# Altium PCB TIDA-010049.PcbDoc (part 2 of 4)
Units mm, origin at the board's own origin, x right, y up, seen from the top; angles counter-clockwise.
Board outline 75 x 60 mm, 4 copper layers (Top Layer, GND, Supply, Bottom Layer), stack 1.565 mm thick; 309 components, 186 nets, 995 pads, 362 vias.
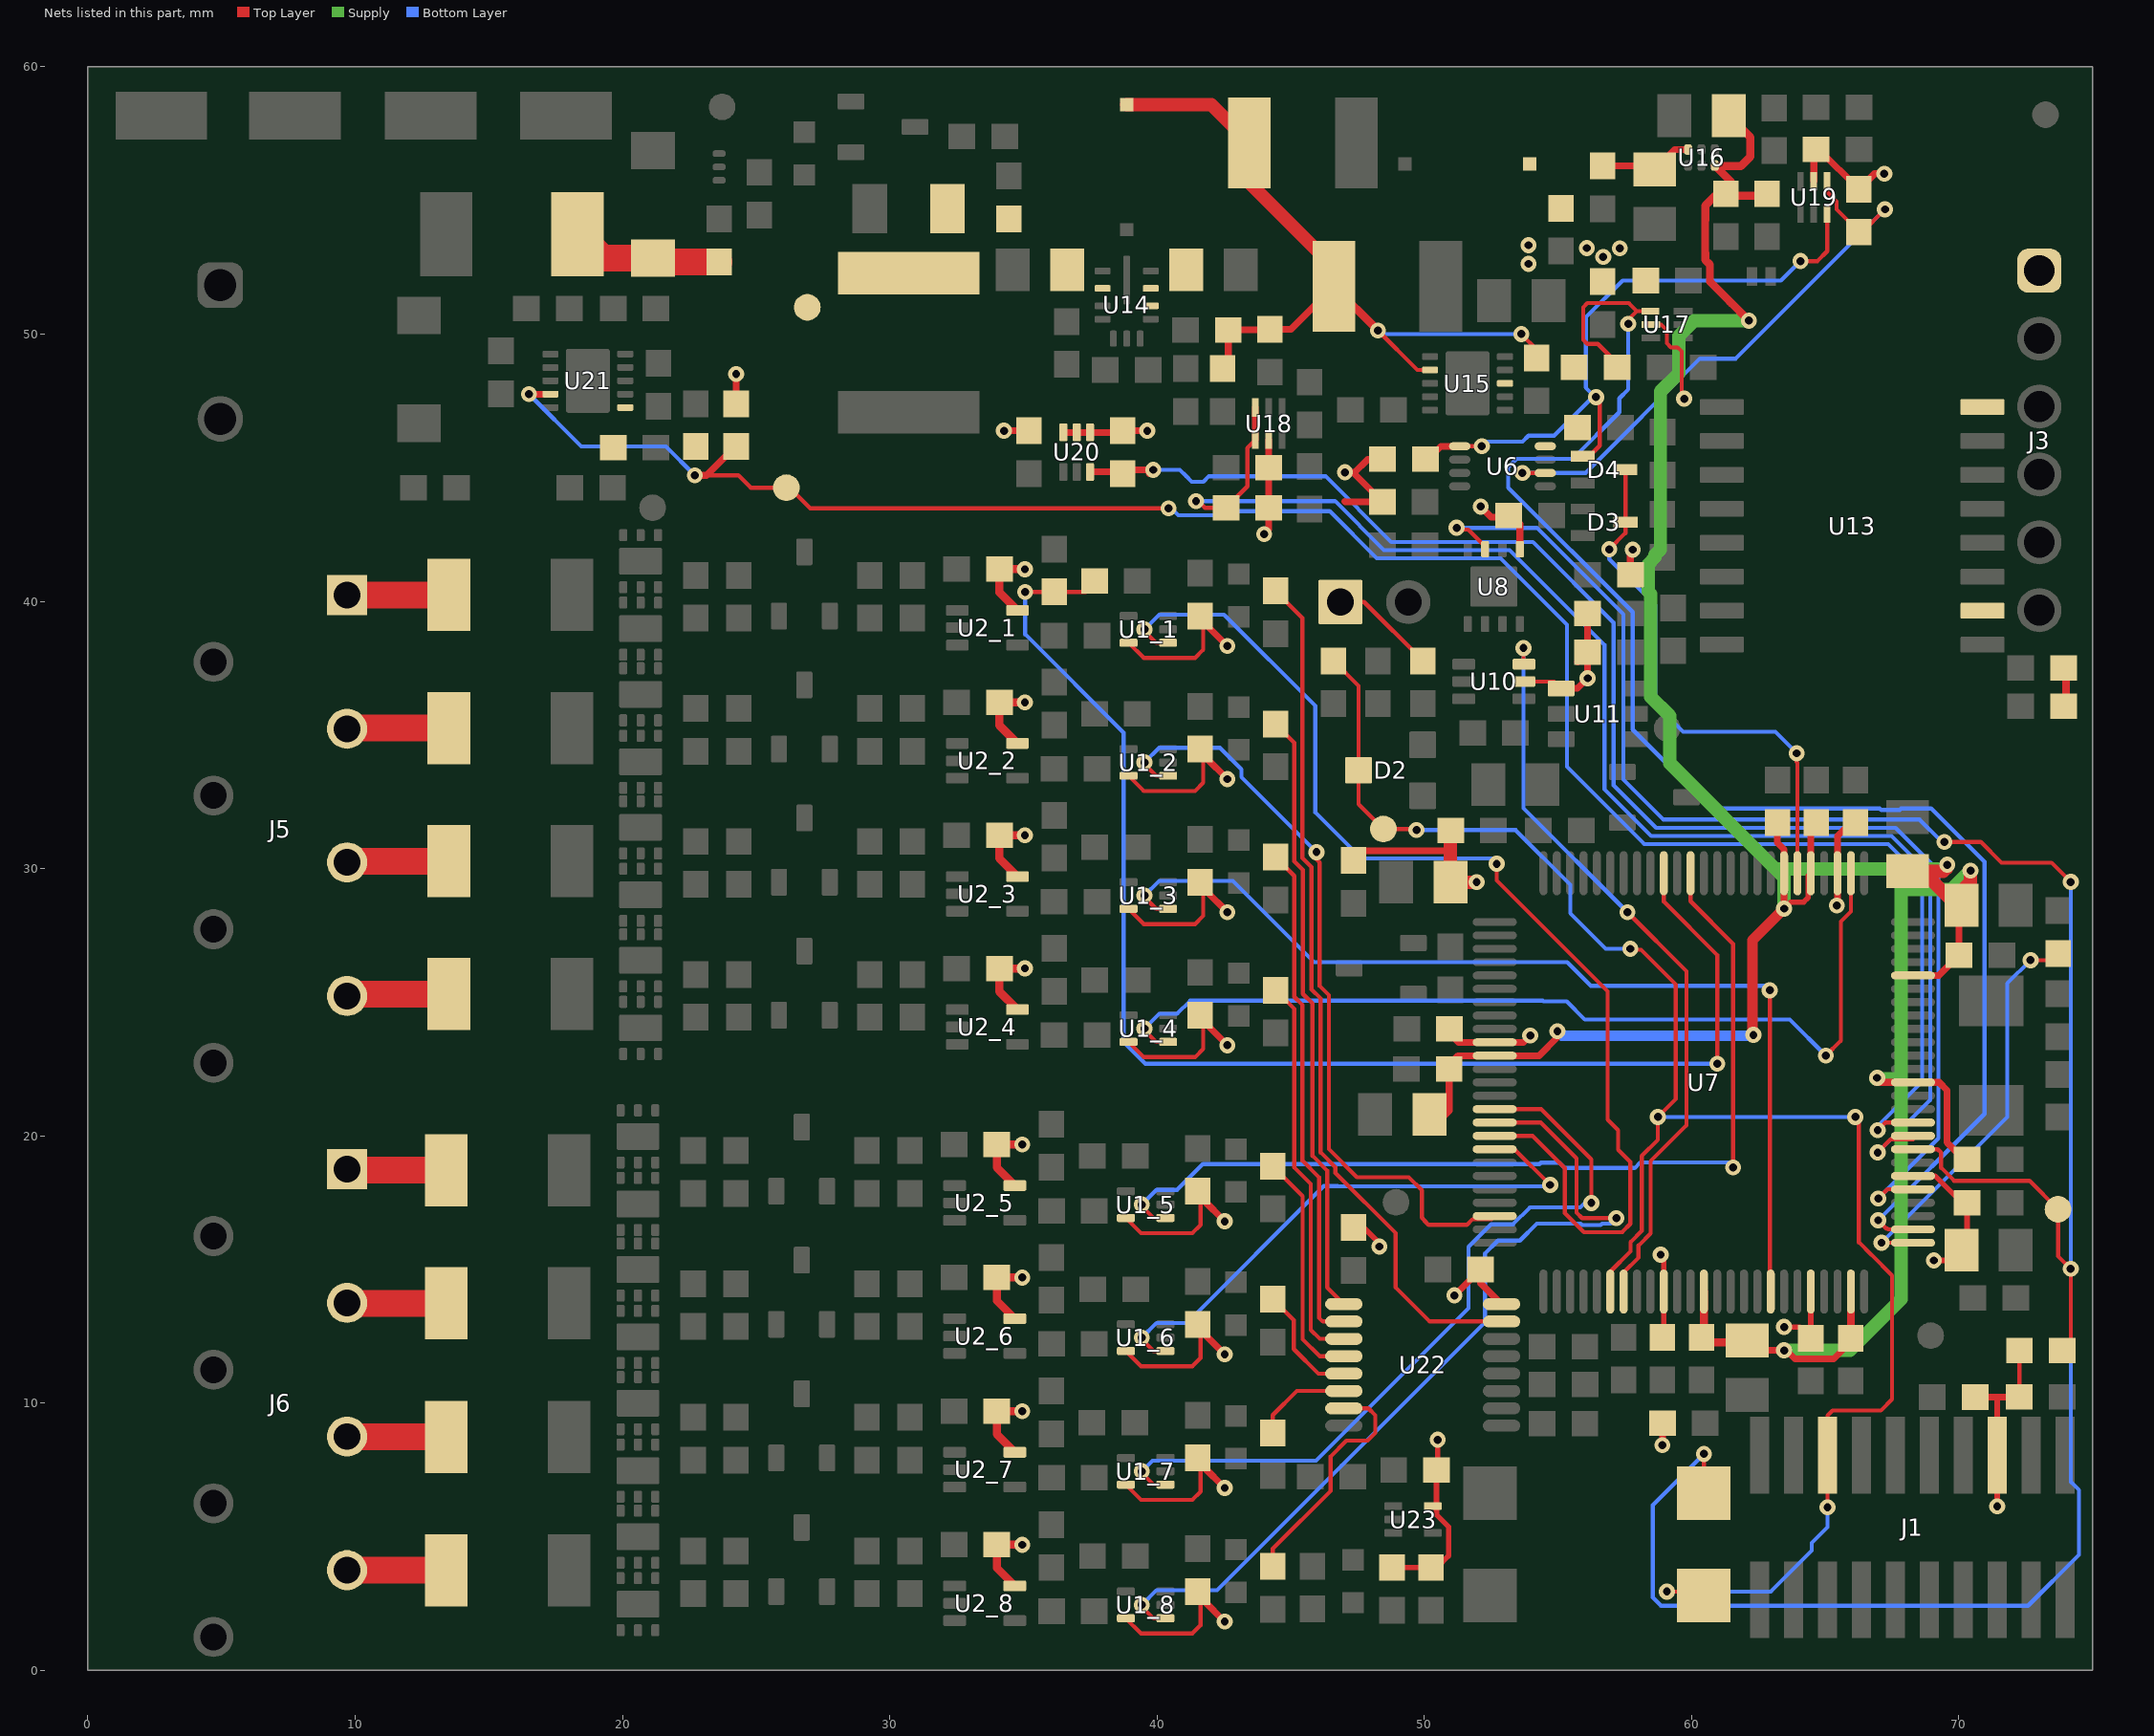
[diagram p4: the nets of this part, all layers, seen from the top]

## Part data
C1_1 C1_2 C1_3 C1_4 C1_5 C1_6 C1_7 C1_8: library part CMP-0007374-4, "CAP, CERM, 0.56 uF, 10 V, +/- 10%, X7R, 0603", Cap_Case=0603, Manufacturer=MuRata, Supplier Part Number 1=GRM188R71A564KA61D-ND, TempCo=X7R, Tolerance_%=10%, Value1=Unknown, Value2=10V, ValueDisplayed=0.56uF
C2_1 C2_2 C2_3 C2_4 C2_5 C2_6 C2_7 C2_8: library part CMP-0006812-4, "CAP, CERM, 100 pF, 10 V, +/- 10%, X7R, 0603", Cap_Case=0603, Manufacturer=AVX, Supplier Part Number 1=0603ZC101KAT2A-ND, TempCo=X7R, Tolerance_%=10%, Value1=Unknown, Value2=10V, ValueDisplayed=100pF
C3_1 C3_2 C3_3 C3_4 C3_5 C3_6 C3_7 C3_8 C4_1 C4_2 C4_3 C4_4 C4_5 C4_6 C4_7 C4_8 C5 C10 C11 C12 C13 C14 C15 C16 C21 C22 C23 C24 C25 C26 C28 C29 C30 C33 C34 C45 C46 C47 C48 C52 C53: library part CMP-0007378-5, "CAP, CERM, 0.1 uF, 16 V, +/- 10%, X7R, 0603", Cap_Case=0603, Manufacturer=MuRata, Supplier Part Number 1=490-1532-1-ND, TempCo=X7R, Tolerance_%=10%, Value1=Unknown, Value2=16V, ValueDisplayed=0.1uF
C6 C7 C8 C9 C19 C20: library part CMP-0064945-2, "CAP, CERM, 10 uF, 6.3 V,+/- 10%, X7R, 0805", Cap_Case=0805, Manufacturer="Taiyo Yuden", Supplier Part Number 1=587-2396-1-ND, TempCo=X7R, Tolerance_%=10%, Value1=Unknown, Value2=6.3V, ValueDisplayed=10uF
C17: library part CMP-0008377-2, "CAP, CERM, 22 uF, 10 V, +/- 20%, X7R, 0805", Cap_Case=0805, Manufacturer=MuRata, Supplier Part Number 1=81-GRM21BZ71A226ME5L, TempCo=X7R, Tolerance_%=20%, Value1=Unknown, Value2=10V, ValueDisplayed=22uF
C18 C27 C42: library part CMP-0007365-4, "CAP, CERM, 1 uF, 10 V, +/- 10%, X7R, 0603", Cap_Case=0603, Manufacturer=MuRata, Supplier Part Number 1=490-3899-1-ND, TempCo=X7R, Tolerance_%=10%, Value1="0.011 ohm", Value2=10V, ValueDisplayed=1uF
C31 C32: library part CMP-0007208-4, "CAP, CERM, 33 pF, 50 V, +/- 5%, C0G/NP0, 0603", Cap_Case=0603, Manufacturer=MuRata, Supplier Part Number 1=490-1415-1-ND, TempCo=C0G/NP0, Tolerance_%=5%, Value1=Unknown, Value2=50V, ValueDisplayed=33pF
C35: library part CMP-0009384-2, "CAP, CERM, 4.7 uF, 100 V, +/- 10%, X7R,", Cap_Case=2220_250, Manufacturer=TDK, Supplier Part Number 1=445-4526-1-ND, TempCo=X7R, Tolerance_%=10%, Value1="0.002349 ohm", Value2=100V, ValueDisplayed=4.7uF
C36 C37: library part CMP-0008249-2, "CAP, CERM, 0.22 uF, 100 V, +/- 10%, X7R, 0805", Cap_Case=0805, Manufacturer=MuRata, Supplier Part Number 1=GRM21AR72A224KAC5-ND, TempCo=X7R, Tolerance_%=10%, Value1=Unknown, Value2=100V, ValueDisplayed=0.22uF
C38: library part CMP-0007196-4, "CAP, CERM, 22 pF, 50 V, +/- 5%, C0G/NP0, 0603", Cap_Case=0603, Manufacturer=MuRata, Supplier Part Number 1=490-1411-1-ND, TempCo=C0G/NP0, Tolerance_%=5%, Value1=Unknown, Value2=50V, ValueDisplayed=22pF
C39 C40: library part CMP-0009348-2, "CAP, CERM, 22 uF, 25 V, +/- 20%, X7R,", Cap_Case=1812_280, Manufacturer=TDK, Supplier Part Number 1=445-1607-1-ND, TempCo=X7R, Tolerance_%=20%, Value1="0.002434 ohm", Value2=25V, ValueDisplayed=22uF
C41: library part CMP-0007112-4, "CAP, CERM, 4.7 uF, 6.3 V, +/- 10%, X7R, 0603", Cap_Case=0603, Manufacturer=Samsung, Supplier Part Number 1=1276-2087-1-ND, TempCo=X7R, Tolerance_%=10%, Value1=Unknown, Value2=6.3V, ValueDisplayed=4.7uF
C43 C44: library part CMP-0008315-2, "CAP, CERM, 10 uF, 10 V, +/- 10%, X7R, 0805", Cap_Case=0805, Manufacturer=MuRata, Supplier Part Number 1=490-3905-1-ND, TempCo=X7R, Tolerance_%=10%, Value1="0.003 ohm", Value2=10V, ValueDisplayed=10uF
C49 C50: library part CMP-0007469-4, "CAP, CERM, 0.1 uF, 100 V, +/- 10%, X7R, 0603", Cap_Case=0603, Manufacturer=MuRata, PartNumber=GRM188R72A104KA35D, Supplier Part Number 1=490-3285-1-ND, TempCo=X7R, Tolerance_%=10%, Value1=Unknown, Value2=100V, ValueDisplayed=0.1uF
C51: library part CMP-0007109-4, "CAP, CERM, 0.01 uF, 50 V, +/- 10%, X7R, 0603", Cap_Case=0603, Manufacturer="Samsung Electro-Mechanics", PartNumber=CL10B103KB8NCNC, Supplier Part Number 1=1276-1921-1-ND, TempCo=X7R, Tolerance_%=10%, Value1=Unknown, Value2=50V, ValueDisplayed=0.01uF
D1_1 D1_2 D1_3 D1_4 D1_5 D1_6 D1_7 D1_8: library part CMP-0002905-2, "LED, Green, SMD", Color=Green, Manufacturer="Wurth Elektronik", Value1=W, Value2=3.2V
D2: library part CMP-0086222-1, "Diode, Switching, 30 V, 0.13 A, SOT23, 3-Leads, Body 2.98x1.6mm, Pitch 0.95mm", Manufacturer=Panasonic, Value1=0.13A, Value2=0.55V
D3: library part CMP-0028454-2, "Diode, Schottky, 30 V, 0.2 A, SOT-523", Manufacturer="Diodes Inc.", Value1=0.2A, Value2=0.7V
D4: library part CMP-0077018-2, "Diode, Schottky, 30 V, 0.2 A, SOT-523", Manufacturer="Diodes Inc.", Value1=0.2A, Value2=1V
D5 D7: library part CMP-0085015-1, "Diode, TVS, Bi, 30 V, 48.4 Vc, 400 W, 8.3 A, SMA (non-polarized)", Manufacturer=Littelfuse, Value1=48.4V
D6: library part CMP-0076931-2, "Diode, Schottky, 30 V, 0.2 A, 1.00x0.50x0.60mm", Manufacturer="Diodes Inc.", Value1=0.2A, Value2=1V
D8: library part CMP-0002894-2, "LED, Green, SMD", Color=green, Manufacturer="Wurth Elektronik", PartNumber=150060VS75000, Value1=W, Value2=2V
D9: library part CMP-0002947-1, "LED, Red, SMD", Color=Red, Manufacturer="Wurth Elektronik", Power_TotalModule=72mW, Supplier Part Number 1=732-4978-1-ND, Value1=0.072W, Value2=2V
F1: library part CMP-0003488-1, "Fuse, 1.5 A, 125VAC/VDC, SMD", Irating_A=1.5A, Manufacturer=Littelfuse
FID1 FID2 FID3: library part CMP-0077181-1, "Fiducial mark.  There is nothing to buy or mount.", Manufacturer=N/A
H1 H2 H3 H4: library part CMP-0003620-1, "Bumpon, Hemisphere, 0.44 X 0.20, Clear", Manufacturer=3M, Supplier Part Number 1=SJ5303-7-ND
J1: library part CMP-0075640-2, "Header, 1.27mm, 10x2, Tin, SMT", Color=Black, Current_A=3.1A, Manufacturer=Samtec, Supplier Part Number 1=SAM8792-ND
J2: library part CMP-0075483-1, "Header, 100mil, 2x1, Gold, TH", Manufacturer=Samtec, Supplier Part Number 1=SAM8736-ND
J3: library part CMP-0054801-2, "Header, 2.54 mm, 6x1, Gold, TH", Color=Black, Manufacturer="Wurth Elektronik", Supplier Part Number 1=732-5319-ND
J4: library part CMP-0055529-1, "Terminal Block, 5mm, 2x1, R/A, TH", Color=Green, Current_A=16A, Manufacturer="Phoenix Contact", Supplier Part Number 1=277-2518-ND, Voltage_V=400V
J5 J6: library part CMP-0055509-1, "Terminal Block, 8x1, 2.5mm, Green, TH", Color=Green, Current_A=2A, Manufacturer="Phoenix Contact", Supplier Part Number 1=277-1800-ND, Voltage_V=300V
L1 L2: library part CMP-0064407-2, "Inductor, Shielded Drum Core, Ferrite, 18 uH, 0.7 A, 0.138 ohm, SMD", Manufacturer="Wurth Elektronik", Supplier Part Number 1=732-1106-1-ND, Value1="0.138 ohm", Value2=0.7A, ValueDisplayed=18uH
L3: library part CMP-0058743-1, "Inductor, Multilayer, Ferrite, 2.2 uH, 0.6 A, 0.34 ohm, SMD", Manufacturer=MuRata, Supplier Part Number 1=490-4994-1-ND, Value1="0.34 ohm", Value2=0.6A, ValueDisplayed=2.2uH
LBL1: library part CMP-0003625-1, "Thermal Transfer Printable Labels, 0.650\" W x 0.200\" H - 10,000 per roll", Manufacturer=Brady, Supplier Part Number 1=97C5133
LOGO1: library part CMP-0074844-1
Logo3: library part CMP-0074847-1, "FCC_disclaimer"
Logo4: library part CMP-0074769-1
Q1: library part CMP-0000824-1, "MOSFET, N-CH, 60 V, 2.2 A, YJK0003A (PICOSTAR-3)", Alternate Manufacturer=None, Manufacturer="Texas Instruments", Supplier Part Number 1=296-44374-1-ND, Value1=0.07, Value2="11 nC"
R1_1 R1_2 R1_3 R1_4 R1_5 R1_6 R1_7 R1_8 R4_1 R4_2 R4_3 R4_4 R4_5 R4_6 R4_7 R4_8 R23: library part CMP-0025752-3, "RES, 200, 5%, 0.1 W, 0603", Manufacturer=Vishay-Dale, Power_W=100mW, Supplier Part Number 1=541-200GCT-ND, TempCo="200 ppm/C", Tolerance_%=5%, Value2=0.1W, Value_Code=200R, ValueDisplayed=200
R2_1 R2_2 R2_3 R2_4 R2_5 R2_6 R2_7 R2_8: library part CMP-0016428-1, "RES, 4.99 k, 1%, 0.75 W, AEC-Q200 Grade 0, 2010", Manufacturer=Vishay-Dale, Power_W=750mW, Supplier Part Number 1=541-4.99KACCT-ND, TempCo="100 ppm/C", Tolerance_%=1%, Value2=0.75W, Value_Code=4k99, ValueDisplayed=4.99k
R3_1 R3_2 R3_3 R3_4 R3_5 R3_6 R3_7 R3_8: library part CMP-0022867-5, "RES, 1.13 k, 1%, 0.1 W, 0603", Manufacturer=Yageo, Power_W=100mW, Supplier Part Number 1=311-1.13KHRCT-ND, TempCo="100 ppm/C", Tolerance_%=1%, Value2=0.1W, Value_Code=1k13, ValueDisplayed=1.13k
R5_1 R5_2 R5_3 R5_4 R5_5 R5_6 R5_7 R5_8: library part CMP-0023233-5, "RES, 66.5, 1%, 0.1 W, 0603", Manufacturer=Yageo, Power_W=100mW, Supplier Part Number 1=311-66.5HRCT-ND, TempCo="100 ppm/C", Tolerance_%=1%, Value2=0.1W, Value_Code=66R5, ValueDisplayed=66.5
R6_1 R6_2 R6_3 R6_4 R6_5 R6_6 R6_7 R6_8 R64: library part CMP-0023284-5, "RES, 806, 1%, 0.1 W, 0603", Manufacturer=Yageo, Power_W=100mW, Supplier Part Number 1=311-806HRCT-ND, TempCo="100 ppm/C", Tolerance_%=1%, Value2=0.1W, Value_Code=806R, ValueDisplayed=806
R7_1 R7_2 R7_3 R7_4 R7_5 R7_6 R7_7 R7_8: library part CMP-0022990-5, "RES, 2.49 k, 1%, 0.1 W, 0603", Manufacturer=Yageo, Power_W=100mW, Supplier Part Number 1=311-2.49KHRCT-ND, TempCo="100 ppm/C", Tolerance_%=1%, Value2=0.1W, Value_Code=2k49, ValueDisplayed=2.49k
R8 R16 R22 R24 R27 R57 R58 R59 R63: library part CMP-0025918-5, "RES, 3.3 k, 5%, 0.1 W, 0603", Manufacturer=Yageo, Power_W=100mW, Supplier Part Number 1=311-3.3KGRCT-ND, TempCo="100 ppm/C", Tolerance_%=5%, Value2=0.1W, Value_Code=3k30, ValueDisplayed=3.3k
R9 R10 R11 R12 R13 R15 R26: library part CMP-0025886-5, "RES, 10 k, 5%, 0.1 W, 0603", Manufacturer=Yageo, Power_W=100mW, Supplier Part Number 1=311-10KGRCT-ND, TempCo="100 ppm/C", Tolerance_%=5%, Value2=0.1W, Value_Code=10k0, ValueDisplayed=10k
R14 R17 R19 R21 R28 R29 R30 R37 R38 R39 R42 R49 R50 R51 R56: library part CMP-0025925-5, "RES, 47 k, 5%, 0.1 W, 0603", Manufacturer=Yageo, Power_W=100mW, Supplier Part Number 1=311-47KGRCT-ND, TempCo="100 ppm/C", Tolerance_%=5%, Value2=0.1W, Value_Code=47k0, ValueDisplayed=47k
R18: library part CMP-0025821-4, "RES, 4.7, 5%, 0.1 W, AEC-Q200 Grade 0, 0603", Manufacturer=Vishay-Dale, Power_W=100mW, Supplier Part Number 1=541-4.7GCT-ND, TempCo="200 ppm/C", Tolerance_%=5%, Value2=0.1W, Value_Code=4R70, ValueDisplayed=4.7
R20: library part CMP-0022984-5, "RES, 2.21 k, 1%, 0.1 W, 0603", Manufacturer=Yageo, Power_W=100mW, Supplier Part Number 1=311-2.21KHRCT-ND, TempCo="100 ppm/C", Tolerance_%=1%, Value2=0.1W, Value_Code=2k21, ValueDisplayed=2.21k
R25: library part CMP-0025899-5, "RES, 1.0 k, 5%, 0.1 W, 0603", Manufacturer=Yageo, Power_W=100mW, Supplier Part Number 1=311-1.0KGRCT-ND, TempCo="100 ppm/C", Tolerance_%=5%, Value2=0.1W, Value_Code=1k00, ValueDisplayed=1.0k
R31: library part CMP-0023291-5, "RES, 82.5 k, 1%, 0.1 W, 0603", Manufacturer=Yageo, Power_W=100mW, Supplier Part Number 1=311-82.5KHRCT-ND, TempCo="100 ppm/C", Tolerance_%=1%, Value2=0.1W, Value_Code=82k5, ValueDisplayed=82.5k
R32: library part CMP-0022900-4, "RES, 1.00, 1%, 0.1 W, 0603", Manufacturer=Yageo, Power_W=100mW, Supplier Part Number 1=311-1.00HRCT-ND, TempCo="200 ppm/C", Tolerance_%=1%, Value2=0.1W, Value_Code=1R00, ValueDisplayed=1.00
R33 R36 R46 R47 R48 R55 R62: library part CMP-0022944-5, "RES, 24.9 k, 1%, 0.1 W, 0603", Manufacturer=Yageo, Power_W=100mW, Supplier Part Number 1=311-24.9KHRCT-ND, TempCo="100 ppm/C", Tolerance_%=1%, Value2=0.1W, Value_Code=24k9, ValueDisplayed=24.9k
R34: library part CMP-0023026-5, "RES, 31.6 k, 1%, 0.1 W, 0603", Manufacturer=Yageo, Power_W=100mW, Supplier Part Number 1=311-31.6KHRCT-ND, TempCo="100 ppm/C", Tolerance_%=1%, Value2=0.1W, Value_Code=31k6, ValueDisplayed=31.6k
R35: library part CMP-0023238-5, "RES, 68.1 k, 1%, 0.1 W, 0603", Manufacturer=Yageo, Power_W=100mW, Supplier Part Number 1=311-68.1KHRCT-ND, TempCo="100 ppm/C", Tolerance_%=1%, Value2=0.1W, Value_Code=68k1, ValueDisplayed=68.1k
R40: library part CMP-0023176-5, "RES, 53.6 k, 1%, 0.1 W, 0603", Manufacturer=Yageo, Power_W=100mW, Supplier Part Number 1=311-53.6KHRCT-ND, TempCo="100 ppm/C", Tolerance_%=1%, Value2=0.1W, Value_Code=53k6, ValueDisplayed=53.6k
R41: library part CMP-0022941-4, "RES, 249 k, 1%, 0.1 W, 0603", Manufacturer=Yageo, Power_W=100mW, Supplier Part Number 1=311-249KHRCT-ND, TempCo="100 ppm/C", Tolerance_%=1%, Value2=0.1W, Value_Code=249k
R43: library part CMP-0022872-5, "RES, 1.24 k, 1%, 0.1 W, 0603", Manufacturer=Yageo, Power_W=100mW, Supplier Part Number 1=311-1.24KHRCT-ND, TempCo="100 ppm/C", Tolerance_%=1%, Value2=0.1W, Value_Code=1k24, ValueDisplayed=1.24k
R44: library part CMP-0022982-5, "RES, 2.15 k, 1%, 0.1 W, 0603", Manufacturer=Yageo, Power_W=100mW, Supplier Part Number 1=311-2.15KHRCT-ND, TempCo="100 ppm/C", Tolerance_%=1%, Value2=0.1W, Value_Code=2k15, ValueDisplayed=2.15k
R45: library part CMP-0022858-4, "RES, 196 k, 1%, 0.1 W, 0603", Manufacturer=Yageo, Power_W=100mW, Supplier Part Number 1=311-196KHRCT-ND, TempCo="100 ppm/C", Tolerance_%=1%, Value2=0.1W, Value_Code=196k
R52: library part CMP-0023184-4, "RES, 562 k, 1%, 0.1 W, 0603", Manufacturer=Yageo, Power_W=100mW, Supplier Part Number 1=311-562KHRCT-ND, TempCo="100 ppm/C", Tolerance_%=1%, Value2=0.1W, Value_Code=562k
R53: library part CMP-0022792-5, "RES, 13.0 k, 1%, 0.1 W, 0603", Manufacturer=Yageo, Power_W=100mW, Supplier Part Number 1=311-13.0KHRCT-ND, TempCo="100 ppm/C", Tolerance_%=1%, Value2=0.1W, Value_Code=13k0, ValueDisplayed=13.0k
R54: library part CMP-0023279-5, "RES, 7.50 k, 1%, 0.1 W, 0603", Manufacturer=Yageo, Power_W=100mW, Supplier Part Number 1=311-7.50KHRCT-ND, TempCo="100 ppm/C", Tolerance_%=1%, Value2=0.1W, Value_Code=7k50, ValueDisplayed=7.50k
R60: library part CMP-0022824-4, "RES, 165 k, 1%, 0.1 W, 0603", Manufacturer=Yageo, Power_W=100mW, Supplier Part Number 1=311-165KHRCT-ND, TempCo="100 ppm/C", Tolerance_%=1%, Value2=0.1W, Value_Code=165k
R61: library part CMP-0017903-2, "RES, 14.7 k, 1%, 0.25 W, 1206", Manufacturer="Yageo America", Power_W=250mW, Supplier Part Number 1=311-14.7KFRCT-ND, TempCo="100 ppm/C", Tolerance_%=1%, Value2=0.25W, Value_Code=14k7, ValueDisplayed=14.7k
S1 S2: library part CMP-0002210-1, "Switch, Tactile, SPST-NO, 0.05A, 12V, SMD", CurrentRating_mA=50A, Manufacturer="C&K Components", Supplier Part Number 1=CKN10388CT-ND
TP6 TP7 TP8 TP9 TP15 TP19 TP20: library part CMP-0003825-1, "1mm Test Point, SMT", Manufacturer=Any
TP11 TP12 TP13 TP14: library part CMP-0055152-1, "Test Point, Miniature, SMT", Manufacturer=Keystone, Supplier Part Number 1=36-5015TR-ND
U1_1 U1_2 U1_3 U1_4 U1_5 U1_6 U1_7 U1_8 U23: library part CMP-0051312-3, "Single Bus Buffer Gate With 3-State Outputs, DRL0005A, LARGE T&R", Alternate Manufacturer="Texas Instruments", F @ Nom Voltage(Max)(Mhz)=150, Generic Part Number=SN74LVC1G125, ICC @ Nom Voltage(Max)(mA)=0.01, Operating Temperature Range(C)="-40 to 125,-40 to 85", Rating=Catalog, tpd @ Nom Voltage(Max)(ns)=9,5.5,4.5,4, Voltage(Nom)(V)=1.8,2.5,3.3,5
U2_1 U2_2 U2_3 U2_4 U2_5 U2_6 U2_7 U2_8: library part CMP-0081556-1, "Low-Power, Rail-to-Rail In and Out, 1-MHz Operational Amplifier, DCK0005A (SOT-SC70-5)", Alternate Manufacturer="Texas Instruments", Alternate PartNumber=TLV9001IDCKT
U3_1 U3_2 U3_3 U3_4 U3_5 U3_6 U3_7 U3_8 U4_1 U4_2 U4_3 U4_4 U4_5 U4_6 U4_7 U4_8: library part CMP-0077837-1, "5-V Precision Surge Protection Clamp, DRV0006A (WSON-6)", Alternate Manufacturer="Texas Instruments"
U5_1 U5_2 U5_3 U5_4 U5_5 U5_6 U5_7 U5_8 U24: library part CMP-0084728-1, "Programmable Shunt Regulator with Optimized Reference Current, DBZ0003A (SOT-23-3)", Alternate Manufacturer="Texas Instruments"
U6: library part CMP-0051919-2, "Dual 2-Input NAND Gate with Schmitt-Trigger Inputs, DCU0008A (VSSOP-8)", F @ Nom Voltage(Max)(Mhz)=150, Generic Part Number=SN74LVC2G132, ICC @ Nom Voltage(Max)(mA)=0.01, Manufacturer="Texas Instruments", Operating Temperature Range="-40 to 125 C", Rating=Catalog, tpd @ Nom Voltage(Max)(ns)=16,7.5,6,5, Voltage(Nom)(V)=1.8,2.5,3.3,5
U7: library part CMP-0076634-2, "16- and 32-Bit RISC Flash Microcontroller, PZ0100A (LQFP-100)", Alternate Manufacturer="Texas Instruments"
U8: library part CMP-0013381-4, "High-Accuracy Voltage Supervisor With Programmable Window Watchdog Timer, DRB0008A (VSON-8)", Alternate Manufacturer="Texas Instruments", Alternate PartNumber=TPS3852H33DRBT, Operating Temperature Range="-40 to 125 C", Rating=Catalog
U9: library part CMP-0032500-1, "3.0 V, 50 ppm / degC, 50 uA Series (Bandgap) Voltage Reference, -40 to 125 degC, 3-pin SOT-23 (DBZ), Green (RoHS & no Sb/Br)", Manufacturer="Texas Instruments", Rating=Catalog, Temp Coeff(Max)(ppm/ degree C)=50, Temp Coeff(Typ)(ppm/ degree C)=20
U10: library part CMP-0051216-3, "Single 3-Input Positive-AND Gate, DCK0006A (SOT-SC70-6)", F @ Nom Voltage(Max)(Mhz)=150, Generic Part Number=SN74LVC1G11, ICC @ Nom Voltage(Max)(mA)=0.01, Manufacturer="Texas Instruments", Operating Temperature Range="-40 to 125,-40 to 85 C", Rating=Catalog, tpd @ Nom Voltage(Max)(ns)=20,7.8,6.2,4.6, Voltage(Nom)(V)=1.8,2.5,3.3,5
U11: library part CMP-0077265-1, "5.5-V, 2-A, 80 mohm Low Leakage Load Switch with RCB and Programmable Rise Time, DBV0006A (SOT-23-6)", Alternate Manufacturer="Texas Instruments", Alternate PartNumber=TPS22917DBVT
U12: library part CMP-0084725-1, "Programmable Shunt Regulator with Optimized Reference Current, DBZ0003A (SOT-23-3)", Alternate Manufacturer="Texas Instruments"
U13: library part CMP-0076065-3, "Automotive, High Speed, Robust EMC Quad-Channel Digital Isolators, DW0016B (SOIC-16)", Alternate Manufacturer="Texas Instruments", Alternate PartNumber=ISO7741FQDWQ1, Operating Temperature Range="-40 to 125 C", Rating=Automotive
U14: library part CMP-0080116-3, "65-V 0.6-A Synchronous Step-Down Converter, RNX0012B (VQFN-HR-12)", Alternate Manufacturer="Texas Instruments", Alternate PartNumber=LMR36006BRNXR
U15: library part CMP-0013400-5, "3V-65V Input, 500mA Synchronous Buck Converter With Ultra-Low Iq, DRC0010J (VSON-10)", Alternate Manufacturer="Texas Instruments", Alternate PartNumber=LM5166YDRCT, Operating Temperature Range="-40 to 150 C", Rating=Catalog
U16: library part CMP-0037816-3, "2 MHz Ultra Small Step Down Converter with DCS-Control in 1x1.5 SON Package, DRY0006A (USON-6)", Manufacturer="Texas Instruments", Operating Temperature Range="-40 to 125 C", Rating=Catalog, Switch Current Limit(Typ)(A)=0.84
U17 U18 U19: library part CMP-0074243-1, "High-Voltage (18V) Window Comparator with Over- and Undervoltage Detection, DSE0006A (WSON-6)", Alternate Manufacturer="Texas Instruments", Alternate PartNumber=TPS3700DSET
U20: library part CMP-0074324-2, "Pin-Selectable Trip Point 1.4V-Capable Family of Temperature Switches, DRL0006A (SOT-OTHER-6)", Alternate Manufacturer="Texas Instruments", Alternate PartNumber=TMP302CDRLT
U21: library part CMP-0013390-6, "60-V, 800-mA Industrial eFuse with Integrated Reverse Polarity Protection, DRC0010J (VSON-10)", Alternate Manufacturer="Texas Instruments", Alternate PartNumber=TPS26624DRCT, Operating Temperature Range="-40 to 125 C", Rating=Catalog
U22: library part CMP-0053860-1, "8-Bit Shift Registers With Output Registers, PW0016A, TUBE", F @ Nom Voltage(Max)(Mhz)=110, Generic Part Number=SN74AHC594, ICC @ Nom Voltage(Max)(mA)=0.04, Manufacturer="Texas Instruments", Operating Temperature Range(C)="-40 to 125", Rating=Catalog, tpd @ Nom Voltage(Max)(ns)="13.9, 10.1", Voltage(Nom)(V)="3.3, 5"
Y1: library part CMP-0004648-3, "Crystal, 16 MHz, 18 pF, SMD", Frequency_Fixed=16MHz, Frequency Stability=+/-30ppm, Manufacturer="Abracon Corporation", Supplier Part Number 1=535-10638-1-ND
ZZ1: library part CMP-0003616-3
ZZ2: library part CMP-0077236-1
ZZ3: library part CMP-0077237-1
ZZ4: library part CMP-0077238-1

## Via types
v1: diameter 0.6, hole 0.3, Top Layer to Bottom Layer, 318 vias
v2: diameter 0.5, hole 0.2, Top Layer to Bottom Layer, 44 vias

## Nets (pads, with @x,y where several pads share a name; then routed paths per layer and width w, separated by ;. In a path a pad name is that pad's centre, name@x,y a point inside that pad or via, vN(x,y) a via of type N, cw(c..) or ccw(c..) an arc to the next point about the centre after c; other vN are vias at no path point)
1.25V: C6.1 C7.1 C8.1 C9.1 C10.1 C11.1 C12.1 C13.1 C14.1 C15.1 C16.1 C41.1 L3.2 R40.1 U7.13 U7.21 U7.30 U7.32 U7.61 U7.88 U7.99 U16.6 | length 121.6
  Top Layer w0.152: 61.432,51.099 61.432,51.21
  Top Layer w0.2: v1(63.458,28.5) 63.706,28.748 64.192,28.748 64.36,28.916 64.36,29.727 U7.30@64.458,29.825
  Top Layer w0.254: C8.1@50.74,20.75 50.929,20.939 C14.1@50.929,22.506 ; C14.1@50.758,22.5 51.258,23 U7.61@52.633,23 54.294,23 54.98,23.686 v1(54.98,23.912) ; C9.1@62.083,12.341 62.158,12.266 62.449,11.975 v1(63.458,11.975) 63.545,11.975 63.867,11.653 65.311,11.653 C16.1@65.958,12.3 ; C13.1@62.958,31.718 63.208,31.468 63.208,30.968 63.458,30.718 U7.32@63.458,29.825 v1(63.458,28.5) ; U7.30@64.458,29.825 C12.1@64.458,31.718 ; v1(66.939,22.173) 66.939,22 U7.13@68.283,22 69.258,22 69.558,21.7 69.558,19.75 C10.1@70.308,19 ; U7.21@68.283,26 69.244,26 C11.1@70.008,26.764 C6.1@70.008,28.541
  Top Layer w0.3: U7.88@60.458,14.175 60.458,12.263 60.461,12.266 C9.1@62.158,12.266 ; U16.6@60.866,56.306 U16.6@60.893,56.278 ; L3.2@61.382,58.174 62.199,57.356 62.199,56.641 61.836,56.278 U16.6@60.893,56.278 ; v1(62.142,50.5) 61.432,51.21 60.683,51.959 60.683,52.599 60.507,52.775 60.507,53.02 60.506,53.022 60.506,54.271 60.507,54.272 60.507,54.799 60.888,55.18 C41.1@61.458,55.18 ; R40.1@62.823,55.246 62.757,55.18 C41.1@61.458,55.18 ; C16.1@65.958,12.3 C16.1@65.958,12.432 U7.99@65.958,14.175 ; U16.6@60.893,56.278 61.458,55.714 C41.1@61.458,55.18
  Top Layer w0.4: v1(62.313,23.776) 62.271,23.818 62.271,27.313 v1(63.458,28.5)
  Top Layer w0.5: C7.1@68.075,29.902 C7.1@68.647,29.902 ; v1(69.563,30.144) 69.563,30.048 69.417,29.902 C7.1@68.647,29.902 ; v1(70.433,29.925) 70.433,29.505 70.008,29.08 70.008,28.541 C7.1@68.647,29.902
  Supply w0.254: v1@66.894,22.128 v1(66.939,22.173)
  Supply w0.5: v1(62.142,50.5) 60.093,50.5 59.522,49.929 59.522,48.536 58.833,47.847 58.833,41.929 58.634,41.73 58.634,41.639 58.371,41.375 58.371,40.374 58.468,40.277 58.468,36.43 59.181,35.717 59.181,33.947 63.137,29.99 ; v1@63.458,11.975 65.927,11.975 67.839,13.887 67.839,22.125 ; v1@63.458,28.5 63.458,29.669 63.137,29.99 ; v1@66.894,22.128 67.837,22.128 67.839,22.125 ; v1(69.563,30.144) 69.41,29.99 63.137,29.99 ; v1(70.433,29.925) 69.717,29.208 67.839,29.208 67.839,22.125
  Bottom Layer w0.4: v1(54.98,23.912) 55.142,23.75 62.287,23.75 v1(62.313,23.776)
3.3V: C3_1.1 C3_2.1 C3_3.1 C3_4.1 C3_5.1 C3_6.1 C3_7.1 C3_8.1 C4_1.1 C4_2.1 C4_3.1 C4_4.1 C4_5.1 C4_6.1 C4_7.1 C4_8.1 C5.1 C19.1 C20.1 C21.1 C22.1 C23.1 C24.1 C25.1 C26.1 C30.1 C33.1 C44.1 C45.1 C46.1 C47.1 C48.1 C52.1 C53.1 J1.5 J2.1 L2.2 R9.2 R10.2 R11.2 R12.2 R13.2 R14.2 R15.2 R16.1 R18.1 R19.2 R23.2 R30.1 R32.2 R37.1 R38.2 R39.2 R42.1 R45.2 R49.2 R50.1 R56.1 U1_1.5 U1_2.5 U1_3.5 U1_4.5 U1_5.5 U1_6.5 U1_7.5 U1_8.5 U2_1.5 U2_2.5 U2_3.5 U2_4.5 U2_5.5 U2_6.5 U2_7.5 U2_8.5 U6.8 U7.6 U7.28 U7.60 U7.85 U7.96 U8.1 U10.5 U11.1 U15.8 U16.3 U17.2 U18.2 U19.2 U20.4 U20.5 U20.6 U22.16 U23.5 | length 149
  Top Layer w0.152: U1_8.5@38.835,1.95 39.404,1.38 41.321,1.38 41.631,1.69 C4_8.1@41.631,2.511 ; U1_6.5@38.835,11.95 39.404,11.38 41.321,11.38 41.631,11.69 C4_6.1@41.631,12.511 ; U1_5.5@38.835,16.928 39.404,16.359 41.321,16.359 41.631,16.668 C4_5.1@41.631,17.489 ; U1_7.5@38.835,6.95 39.404,6.38 41.321,6.38 41.631,6.69 C4_7.1@41.631,7.511 ; U1_4.5@38.935,23.514 39.505,22.944 41.421,22.944 41.731,23.254 C4_4.1@41.731,24.075 ; U1_3.5@38.935,28.493 39.505,27.923 41.421,27.923 41.731,28.233 C4_3.1@41.731,29.053 ; U1_2.5@38.935,33.471 39.505,32.902 41.421,32.902 41.731,33.211 C4_2.1@41.731,34.032 ; U1_1.5@38.935,38.45 39.505,37.88 41.421,37.88 41.731,38.19 C4_1.1@41.731,39.011 ; J2.1@46.861,39.974 47.746,39.974 R19.2@49.949,37.771 ; U10.5@53.725,37 54.858,37 U11.1@55.118,36.74 ; U17.2@58.483,50.355 58.857,50.355 59.073,50.139 59.073,49.656 59.229,49.5 59.478,49.5 59.627,49.352 v1@59.627,47.461 ; v1@59.721,47.366 v1(59.721,47.58) ; R11.2@72.249,10.225 R11.2@72.258,10.234 72.264,10.24 R14.2@72.264,11.975
  Top Layer w0.203: R56.1@47.347,16.568 47.726,16.568 48.316,15.979 v1(48.316,15.859) ; R10.2@48.791,3.85 R13.2@50.249,3.85 50.471,3.85 50.908,4.286 50.908,5.373 50.454,5.827 50.454,7.287 50.5,7.334 v1(50.5,8.63) ; v1(58.843,15.555) 58.958,15.555 U7.85@58.958,14.175 C24.1@58.958,12.263 ; v1(63.458,12.85) 64.04,12.85 C25.1@64.458,12.432 ; C25.1@64.458,12.3 C25.1@64.458,12.432 ; U7.96@64.458,14.175 C25.1@64.458,12.432 ; U7.6@68.283,18.5 69.108,18.5 70.108,17.5 C21.1@70.308,17.5 70.308,15.859 C20.1@70.442,15.725 ; v1(69.065,15.341) 69.708,15.341 C20.1@70.092,15.725 ; v1(71.433,6.136) J1.5@71.433,8.055 71.433,10.225 ; 71.433,10.234 R11.2@72.258,10.234
  Top Layer w0.254: R49.2@24.256,47.42 v1(24.256,48.501) ; v1(34.274,46.38) C48.1@35.208,46.38 ; U20.6@36.494,46.32 U20.5@36.994,46.32 U20.4@37.494,46.32 38.648,46.32 R50.1@38.708,46.38 v1(39.637,46.38) ; C4_8.1@41.735,2.732 41.735,2.624 v1(42.533,1.825) ; C4_7.1@41.735,7.732 41.735,7.624 v1(42.534,6.825) ; C4_6.1@41.735,12.731 41.735,12.624 v1(42.533,11.825) ; C4_5.1@41.735,17.71 41.735,17.602 v1(42.533,16.803) ; C4_4.1@41.835,24.296 41.835,24.188 v1(42.634,23.389) ; C4_3.1@41.835,29.274 41.835,29.167 v1(42.634,28.368) ; C4_2.1@41.835,34.253 41.835,34.145 v1(42.634,33.346) ; C4_1.1@41.835,39.231 41.835,39.124 v1(42.634,38.325) ; v1(44.008,42.511) 44.183,42.686 R37.1@44.183,43.5 C46.1@44.183,45 U18.2@44.183,46.055 ; 47.023,43.741 47.043,43.72 R15.2@48.429,43.72 47.362,44.788 ; v1(47.033,44.825) 47.325,44.825 47.362,44.788 ; R23.2@47.347,30.3 47.718,30.671 50.803,30.671 50.974,30.5 ; R38.2@48.439,45.316 47.89,45.316 47.362,44.788 ; C23.1@50.758,24.014 51.272,23.5 U7.60@52.633,23.5 53.707,23.5 v1(53.965,23.757) ; v1(51.128,14.029) 52.099,15 C52.1@52.108,15 52.108,14.486 U22.16@52.889,13.705 ; v1(52.108,43.546) 52.504,43.15 53.325,43.15 53.575,42.9 U8.1@53.575,41.95 ; U11.1@55.118,36.74 55.727,36.74 v1(56.108,37.121) C26.1@56.108,38.1 ; C26.1@55.74,37.732 C26.1@56.108,38.1 ; C30.1@56.108,39.548 C26.1@56.108,38.1 ; R30.1@56.666,56.382 R30.1@56.666,56.29 58.482,56.29 C44.1@58.616,56.155 59.367,56.906 U16.3@59.866,56.906 ; R16.1@57.708,41 57.708,41.847 v1(57.794,41.933) ; v1(58.908,8.425) R9.2@58.908,9.25 ; U19.2@64.573,55.713 64.573,56.821 C47.1@64.658,56.906 64.767,56.906 R39.2@66.258,55.415 66.843,56 v1(67.208,56) ; v1(65.429,28.614) v1(65.429,28.614) 65.458,28.612 U7.28@65.458,29.825 65.458,31.218 C22.1@65.958,31.718 ; R12.2@70.605,10.225 71.433,10.225 R11.2@72.249,10.225
  Top Layer w0.305: U2_8.5@34.679,3.161 34.003,3.837 C3_8.1@34.003,4.7 v1(34.958,4.7) ; U2_7.5@34.679,8.161 34.003,8.837 C3_7.1@34.003,9.7 v1(34.958,9.7) ; U2_6.5@34.679,13.161 34.003,13.837 C3_6.1@34.003,14.7 v1(34.958,14.7) ; U2_5.5@34.679,18.14 34.003,18.815 C3_5.1@34.003,19.678 v1(34.958,19.678) ; U2_4.5@34.779,24.726 34.104,25.401 C3_4.1@34.104,26.264 v1(35.058,26.264) ; U2_3.5@34.779,29.704 34.104,30.38 C3_3.1@34.104,31.243 v1(35.058,31.243) ; U2_2.5@34.779,34.683 34.104,35.358 C3_2.1@34.104,36.221 v1(35.058,36.221) ; U2_1.5@34.779,39.661 34.104,40.337 C3_1.1@34.104,41.2 v1(35.058,41.2)
  Top Layer w0.5: R18.1@51.066,31.543 50.974,31.451 50.974,30.5 C19.1@50.974,29.493 v1(51.958,29.493)
  Supply w0.254: v1(53.965,23.757) v1@54.008,23.714 ; v1(67.208,56) v1@67.208,56.139
  Bottom Layer w0.254: v1@65.429,28.584 v1(65.429,28.614)
  other v1: 53.9,52.625 56.691,52.881 56.083,53.218 57.312,53.207 53.9,53.325
4.3V: C38.1 C39.1 C40.1 L1.2 R29.1 R31.1 R41.1 U15.2 | length 30
  Top Layer w0.152: v1(48.266,50.132) 49.744,48.655 U15.2@50.216,48.655 ; v1(53.625,50) 54.208,49.417 R29.1@54.208,49.102
  Top Layer w0.254: C38.1@42.583,48.705 42.666,48.788 R31.1@42.666,50.155 R41.1@44.112,50.155 ; R41.1@44.217,50.176 45.01,50.176 C40.1@46.616,51.782
  Top Layer w0.3: C40.1@46.616,51.782 v1(48.266,50.132)
  Top Layer w0.5: L1.2@38.866,58.58 42.036,58.58 C39.1@43.458,57.158 C39.1@43.458,56.29 ; C39.1@42.958,55.79 C39.1@43.458,56.29 ; C40.1@46.616,51.782 46.616,52.498 43.458,55.656 C39.1@43.458,56.29
  Bottom Layer w0.152: v1(48.266,50.132) 48.399,50 v1(53.625,50)
24V: C35.1 C36.1 C37.1 C49.1 D5.2 F1.1 R35.2 R52.1 R60.1 R61.1 TP15.1 U14.2 U14.9 U14.10 U21.1 | length 5.7
  Top Layer w1: F1.1@18.366,53.742 19.273,52.835 D5.2@21.139,52.835 21.274,52.7 R35.2@23.616,52.7
/COLD_RST: D3.3 D4.3 U7.31 | length 20.3
  Top Layer w0.152: v1(56.917,41.946) 57.524,42.553 D4.3@57.524,44.927 ; v1(63.933,34.315) 63.933,33.991 63.954,33.969 63.954,29.829 U7.31@63.958,29.825
  Bottom Layer w0.152: v1(56.917,41.946) 56.917,41.578 58.641,39.854 58.641,36.154 59.68,35.115 63.133,35.115 v1(63.933,34.315)
/DIAG_EN1: U1_1.1 U7.67 | length 44.8
  Top Layer w0.152: v1(39.531,38.95) 39.467,38.95 39.967,38.45 U1_1.1@40.415,38.45 ; U7.67@51.923,20 U7.67@52.633,20 54.051,20 55.255,18.796 55.255,17.108 55.97,16.394 57.408,16.394 57.408,16.407 57.707,16.706 57.707,19.023 57.25,19.481 57.25,20.213 56.857,20.606 56.857,25.409 52.708,29.558 v1(52.708,30.18)
  Bottom Layer w0.152: v1(39.531,38.95) 40.081,39.5 42.506,39.5 45.926,36.08 45.926,32.099 47.649,30.375 52.513,30.375 v1(52.708,30.18)
/DIAG_EN2: U1_2.1 U7.73 | length 29.3
  Top Layer w0.152: v1(39.531,33.971) 39.467,33.971 39.967,33.471 U1_2.1@40.415,33.471 ; v1@45.759,30.553 45.744,30.568 45.793,30.617 v1(45.968,30.617) ; v1@45.832,30.48 46.086,30.226 46.086,25.608 46.427,25.267 46.427,19.503 47.477,18.452 49.417,18.452 49.907,17.963 49.907,16.939 50,16.846 50,16.831 50.162,16.668 51.591,16.668 51.801,16.879 52.512,16.879 U7.73@52.633,17
  Bottom Layer w0.152: v1(39.531,33.971) 40.081,34.521 42.35,34.521 43.16,33.712 43.16,33.424 v1(45.968,30.617)
/DIAG_EN3: U1_3.1 U7.93 | length 37.8
  Top Layer w0.152: v1(39.531,28.993) 39.467,28.993 39.967,28.493 U1_3.1@40.415,28.493 ; v1(62.924,25.448) 62.924,14.209 U7.93@62.958,14.175
  Bottom Layer w0.152: v1(39.531,28.993) 40.081,29.543 42.837,29.543 45.88,26.5 53.93,26.5 53.931,26.501 54.369,26.501 54.37,26.5 55.345,26.5 56.23,25.615 62.756,25.615 v1(62.924,25.448)
/DIAG_EN4: U1_4.1 U7.27 | length 35.2
  Top Layer w0.152: v1(39.531,24.014) 39.467,24.014 39.967,23.514 U1_4.1@40.415,23.514 ; v1(65.023,23) 65.583,23.56 65.583,28.02 65.958,28.395 U7.27@65.958,29.825
  Bottom Layer w0.152: v1(39.531,24.014) 40.081,24.564 40.75,24.564 41.24,25.055 54.428,25.055 54.452,25.031 55.328,25.031 56.004,24.355 63.668,24.355 v1(65.023,23)
/DIAG_EN5: U1_5.1 U7.39 | length 35.9
  Top Layer w0.152: v1(39.43,17.428) 39.366,17.428 39.866,16.928 U1_5.1@40.315,16.928 ; U7.39@59.958,29.825 59.958,28.777 61.553,27.182 v1(61.553,18.818)
  Bottom Layer w0.152: v1(39.43,17.428) 39.98,17.978 40.75,17.978 41.714,18.943 54.307,18.943 54.363,18.998 55.053,18.998 55.256,18.795 57.871,18.795 58.079,19.003 61.368,19.003 v1(61.553,18.818)
/DIAG_EN6: U1_6.1 U7.68 | length 21.6
  Top Layer w0.152: v1(39.43,12.45) 39.366,12.45 39.866,11.95 U1_6.1@40.315,11.95 ; U7.68@52.633,19.5 53.373,19.5 v1(54.708,18.165) v1@54.873,18.165
  Bottom Layer w0.152: v1(39.43,12.45) 39.98,13 41.114,13 46.237,18.123 46.75,18.123 v1@54.423,18.115 ; v1(54.708,18.165) v1@54.918,18.165
/DIAG_EN7: U1_7.1 U7.65 | length 29.6
  Top Layer w0.152: v1(39.431,7.45) 39.366,7.45 39.866,6.95 U1_7.1@40.315,6.95 ; U7.65@52.633,21 54.37,21 56.25,19.12 v1(56.25,17.489)
  Bottom Layer w0.152: v1(39.431,7.45) 39.829,7.848 45.952,7.848 51.657,13.554 51.657,15.848 52.502,16.693 53.321,16.693 53.956,17.327 55.835,17.327 55.997,17.489 v1(56.25,17.489)
/DIAG_EN8: U1_8.1 U7.66 | length 33.7
  Top Layer w0.152: v1(39.43,2.45) 39.366,2.45 39.866,1.95 U1_8.1@40.315,1.95 ; U7.66@52.633,20.5 54.352,20.5 55.697,19.156 55.697,17.13 55.903,16.924 v1(57.181,16.924)
  Bottom Layer w0.152: v1(39.43,2.45) 39.98,3 42.25,3 52.267,13.017 52.267,15.595 52.755,16.083 53.574,16.083 54.208,16.718 55.85,16.718 55.907,16.661 56.593,16.661 56.65,16.718 56.975,16.718 v1(57.181,16.924)
/ERROR: U7.82 U10.6 | length 28.4
  Top Layer w0.152: v1(53.708,38.25) 53.708,37.667 U10.6@53.725,37.65 ; U7.82@57.458,14.175 57.458,14.893 58.014,15.45 58.014,15.898 58.468,16.352 58.468,19.054 59.808,20.394 59.808,26.158 v1(57.6,28.366)
  Bottom Layer w0.152: v1@53.758,38.3 53.708,38.35 v1(53.708,38.25) 53.708,32.258 v1(57.6,28.366)
/FLT_1.25V_OV: R39.1 U6.6 U19.1 | length 22.2
  Top Layer w0.152: v1(53.669,44.8) U6.6@54.525,44.8 ; U19.1@65.073,55.733 65.073,55.308 65.424,54.957 65.424,54.661 66.258,53.828 R39.1@66.258,53.815 66.383,53.815 v1(67.233,54.665)
  Bottom Layer w0.152: v1(53.669,44.8) 56.034,44.8 60.314,49.08 61.648,49.08 v1(67.233,54.665)
/FLT_1.25V_UV: D4.1 R38.1 U6.1 U19.6 | length 24.6
  Top Layer w0.152: U6.1@51.325,45.8 v1(52.15,45.8) ; D4.1@55.924,45.427 56.166,45.427 56.56,45.821 v1@56.56,47.639 ; v1(64.07,52.729) 64.704,52.729 65.073,53.098 U19.6@65.073,54.513
  Top Layer w0.254: R38.1@50.066,45.25 50.616,45.8 U6.1@51.325,45.8
  Bottom Layer w0.152: v1(52.15,45.8) 52.324,45.974 53.676,45.974 53.9,46.197 54.851,46.197 56.292,47.639 v1@56.4,47.639 ; v1(56.424,47.639) v1@56.4,47.639 ; v1(64.07,52.729) 63.341,52 57.417,52 56.039,50.622 56.039,48 v1@56.4,47.639
/FLT_3.3V_OV: R42.2 U7.2 U17.1 | length 58.2
  Top Layer w0.152: R42.2@57.258,48.864 56.493,49.629 56.096,49.629 55.941,49.784 55.941,51 56.099,51.157 57.649,51.157 57.952,50.855 ; v1@57.6,50.355 v1(57.63,50.385) 57.63,50.533 57.952,50.855 ; U17.1@58.463,50.855 57.952,50.855 ; v1(66.977,16.84) 67.288,16.529 67.323,16.529 67.351,16.5 U7.2@68.283,16.5
  Bottom Layer w0.152: v1(57.63,50.385) 57.63,47.927 57.297,47.594 57.297,47.072 55.554,45.329 53.45,45.329 53.14,45.019 53.14,44.25 57.794,39.597 57.794,35.199 60.743,32.25 67.037,32.25 67.094,32.193 67.78,32.193 67.838,32.25 68.958,32.25 70.958,30.25 70.958,30.147 70.962,30.143 70.962,29.706 70.958,29.702 70.958,20.821 v1(66.977,16.84)
/FLT_4.3V: R37.2 U7.9 U18.1 U18.6 | length 54.7
  Top Layer w0.152: v1(41.458,43.75) 41.483,43.775 41.516,43.775 41.791,43.5 R37.2@42.583,43.5 43.383,44.3 43.383,45.735 U18.1@43.683,46.035 ; v1(66.963,19.376) 66.963,19.387 67.452,19.876 68.283,19.876 U7.9@68.283,20
  Top Layer w0.254: U18.1@43.683,46.035 U18.6@43.683,47.255
  Bottom Layer w0.152: v1(41.458,43.75) 46.658,43.75 48.492,41.917 53.192,41.917 56.737,38.371 56.737,32.976 58.49,31.223 67.477,31.223 68.735,29.964 68.735,29.801 68.93,29.606 68.93,21.343 v1(66.963,19.376)
/FLT_SENSSUP: R49.1 TP20.1 U7.10 U21.9 | length 76.7
  Top Layer w0.152: 23.151,44.714 24.34,44.714 24.804,44.25 TP20.1@26.135,44.25 ; TP20.1@26.196,44.312 27.031,43.477 v1(40.432,43.477) ; v1(66.963,20.213) 67.25,20.5 U7.10@68.283,20.5
  Top Layer w0.254: v1(16.506,47.75) U21.9@17.308,47.75 ; v1(22.708,44.714) 23.151,44.714 R49.1@24.256,45.82
  Bottom Layer w0.152: v1(16.506,47.75) 18.459,45.797 21.626,45.797 v1(22.708,44.714) ; v1(40.432,43.477) 40.545,43.477 40.801,43.221 42.405,43.221 42.559,43.375 46.459,43.375 48.222,41.612 52.848,41.612 55.338,39.122 55.338,33.81 58.23,30.918 67.35,30.918 68.432,29.836 68.432,29.675 68.625,29.483 68.625,22.03 66.963,20.368 v1(66.963,20.213)
/FLT_TEMP: R50.2 U7.5 U20.3 | length 56.7
  Top Layer w0.152: v1(66.983,17.657) 67.326,18 U7.5@68.283,18
  Top Layer w0.254: U20.3@37.494,44.84 38.648,44.84 R50.2@38.708,44.78 38.808,44.68 39.046,44.918 v1(39.857,44.918) 39.852,44.918 v1@39.713,44.78
  Bottom Layer w0.152: v1(39.857,44.918) 40.854,44.918 41.092,44.68 41.298,44.474 41.734,44.474 41.94,44.68 46.303,44.68 48.762,42.221 54.062,42.221 57.083,39.2 57.083,33.115 58.67,31.527 67.631,31.527 69.037,30.121 69.037,29.926 69.234,29.729 69.234,19.908 v1(66.983,17.657)
/SAFE_STATE: R24.2 U7.1 | length 15.3
  Top Layer w0.152: v1@66.983,16 v1(67.104,16) U7.1@68.283,16 ; v1@72.658,26.415 v1@72.658,26.419 ; v1(72.679,26.574) 73.457,26.574 R24.2@73.708,26.825
  Bottom Layer w0.152: v1(67.104,16) 71.811,20.708 71.811,25.706 v1(72.679,26.574)
/TST_RST: R14.1 S1.2 TP6.1 U7.8 U8.3 | length 95.6
  Top Layer w0.152: v1(51.208,42.75) 51.277,42.681 51.643,42.681 52.275,42.049 U8.3@52.275,41.95 ; S1.2@60.458,6.625 v1(60.458,8.1) ; U7.8@68.283,19.5 69.206,19.5 69.334,19.372 69.334,18.804 69.817,18.322 72.636,18.322 TP6.1@73.708,17.25 73.708,15.504 v1(74.183,15.029) 74.183,12.294 R14.1@73.864,11.975 ; v1(69.458,31) 70.813,31 71.595,30.218 73.465,30.218 v1(74.183,29.5)
  Bottom Layer w0.152: v1(51.208,42.75) 54.21,42.75 57.446,39.513 57.446,33.329 58.944,31.832 68.526,31.832 69.358,31 v1(69.458,31) ; v1(60.458,8.1) 58.544,6.186 58.544,2.731 58.854,2.421 72.583,2.421 74.487,4.325 74.487,6.75 74.183,7.054 v1(74.183,15.029) v1(74.183,29.5)
/WARM_RST: D2.3 J1.15 R25.2 S2.2 TP9.1 U7.81 | length 67.6
  Top Layer w0.152: R25.2@46.607,37.771 47.539,36.839 D2.3@47.539,33.679 47.539,32.408 TP9.1@48.466,31.481 49.674,31.481 v1(49.708,31.446) ; U7.81@56.958,14.175 56.958,14.921 57.712,15.675 57.712,16.024 58.135,16.447 58.135,19.25 58.737,19.852 v1(58.737,20.708) 59.41,21.38 59.41,25.659 58.108,26.961 57.636,26.961 57.676,27 v1(57.708,27) ; v1(59.073,2.95) S2.2@60.458,2.95 ; v1(65.083,6.1) J1.15@65.083,8.055 65.083,9.537 65.271,9.725 67.081,9.725 67.5,10.144 67.5,14.774 66.741,15.533 66.738,15.533 66.258,16.013 66.258,20.574 v1(66.124,20.708)
  Bottom Layer w0.152: v1(49.708,31.446) 53.423,31.446 53.423,31.427 55.458,29.392 55.458,28.328 56.786,27 v1(57.708,27) ; v1(58.737,20.708) v1(66.124,20.708) ; v1(59.073,2.95) 62.961,2.95 64.494,4.484 64.494,4.77 65.083,5.359 v1(65.083,6.1)
DGND: C28.2 J3.1 R28.2 U13.2 U13.8 | length 1.5
  Top Layer w0.3: R28.2@74.008,36.171 C28.2@74.008,37.668
DI_IN1: J5.1 R2_1.2 | length 3.8
  Top Layer w1: J5.1@9.7,40.232 9.705,40.236 R2_1.2@13.508,40.236 R2_1.2@13.495,40.25
DI_IN2: J5.3 R2_2.2 | length 3.8
  Top Layer w1: J5.3@9.7,35.232 9.726,35.258 R2_2.2@13.508,35.258 R2_2.2@13.495,35.271
DI_IN3: J5.5 R2_3.2 | length 3.8
  Top Layer w1: J5.5@9.7,30.232 9.747,30.279 R2_3.2@13.508,30.279 R2_3.2@13.495,30.293
DI_IN4: J5.7 R2_4.2 | length 3.9
  Top Layer w1: J5.7@9.7,25.232 9.769,25.301 R2_4.2@13.508,25.301 R2_4.2@13.495,25.314
DI_IN5: J6.1 R2_5.2 | length 3.7
  Top Layer w1: J6.1@9.7,18.75 9.735,18.715 R2_5.2@13.408,18.715 R2_5.2@13.394,18.728
DI_IN6: J6.3 R2_6.2 | length 3.7
  Top Layer w1: J6.3@9.7,13.75 9.714,13.736 R2_6.2@13.408,13.736 R2_6.2@13.394,13.75
DI_IN7: J6.5 R2_7.2 | length 3.7
  Top Layer w1: J6.5@9.7,8.75 9.714,8.736 R2_7.2@13.408,8.736 R2_7.2@13.395,8.75
DI_IN8: J6.7 R2_8.2 | length 3.7
  Top Layer w1: J6.7@9.7,3.75 13.394,3.75 R2_8.2@13.408,3.736
DI_LED1: R6_1.2 U22.15 | length 32.4
  Top Layer w0.152: R6_1.2@44.431,40.387 45.439,39.379 45.439,30.398 45.781,30.056 45.781,25.482 46.122,25.14 46.122,19.376 46.67,18.829 46.67,18.616 48.929,16.357 48.929,14.326 50.2,13.055 U22.15@52.889,13.055
DI_LED2: R6_2.2 U22.1 | length 22.8
  Top Layer w0.152: R6_2.2@44.431,35.408 45.135,34.705 45.135,30.271 45.458,29.948 45.458,25.309 45.818,24.949 45.818,19.25 46.365,18.702 46.365,14.329 U22.1@46.989,13.705
DI_LED3: R6_3.2 U22.2 | length 18.9
  Top Layer w0.152: R6_3.2@44.431,30.43 45.135,29.726 45.135,25.201 45.442,24.893 45.442,19.07 46.06,18.452 46.06,13.198 46.203,13.055 U22.2@46.989,13.055
DI_LED4: R6_4.2 U22.3 | length 14.6
  Top Layer w0.152: R6_4.2@44.431,25.451 45.138,24.745 45.138,18.814 45.756,18.197 45.756,12.737 46.088,12.405 U22.3@46.989,12.405
DI_LED5: R6_5.2 U22.4 | length 8.7
  Top Layer w0.152: R6_5.2@44.33,18.866 45.451,17.745 45.451,12.392 46.088,11.755 U22.4@46.989,11.755
DI_LED6: R6_6.2 U22.5 | length 4.4
  Top Layer w0.152: R6_6.2@44.33,13.887 45.117,13.101 45.117,12.024 46.035,11.105 U22.5@46.989,11.105
DI_LED7: R6_7.2 U22.6 | length 3.7
  Top Layer w0.152: R6_7.2@44.331,8.887 44.331,9.553 45.233,10.455 U22.6@46.989,10.455
DI_LED8: R6_8.2 U22.7 | length 9
  Top Layer w0.152: R6_8.2@44.33,3.887 44.33,4.553 46.497,6.719 46.497,8.011 47.082,8.597 47.88,8.597 48.167,8.884 48.167,9.546 47.908,9.805 U22.7@46.989,9.805
DI_LOGIC1: C1_1.1 R4_1.2 U7.41 | length 52.1
  Top Layer w0.152: v1(35.07,40.35) C1_1.1@36.152,40.35 37.342,40.35 R4_1.2@37.563,40.571 ; R4_1.2@37.308,40.825 R4_1.2@37.563,40.571 ; R4_1.2@37.667,40.55 37.583,40.55 R4_1.2@37.563,40.571 ; U7.41@58.958,29.825 58.958,28.764 60.958,26.764 v1(60.958,22.7)
  Bottom Layer w0.152: v1@35.277,40.35 v1(35.07,40.35) 35.07,38.762 38.75,35.081 38.75,23.513 39.563,22.7 v1(60.958,22.7)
